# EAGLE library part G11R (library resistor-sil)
SIL RESISTOR
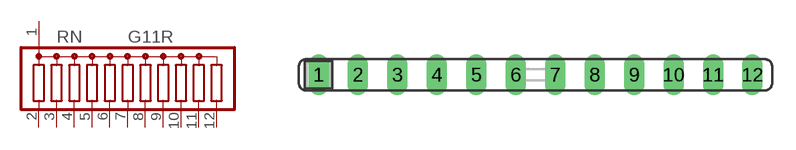
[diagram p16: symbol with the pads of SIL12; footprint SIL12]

Designator prefix RN

## G11R (OC_FARNELL: unknown; OC_NEWARK: unknown)  [SIL12]
1  1  pas
2  2  pas
3  3  pas
4  4  pas
5  5  pas
6  6  pas
7  7  pas
8  8  pas
9  9  pas
10  10  pas
11  11  pas
12  12  pas

## Footprint SIL12 (pad centres in mm)
Single In Line
drill 0.813 long: 1 -13.97,0; 2 -11.43,0; 3 -8.89,0; 4 -6.35,0; 5 -3.81,0; 6 -1.27,0; 7 1.27,0; 8 3.81,0; 9 6.35,0; 10 8.89,0; 11 11.43,0; 12 13.97,0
